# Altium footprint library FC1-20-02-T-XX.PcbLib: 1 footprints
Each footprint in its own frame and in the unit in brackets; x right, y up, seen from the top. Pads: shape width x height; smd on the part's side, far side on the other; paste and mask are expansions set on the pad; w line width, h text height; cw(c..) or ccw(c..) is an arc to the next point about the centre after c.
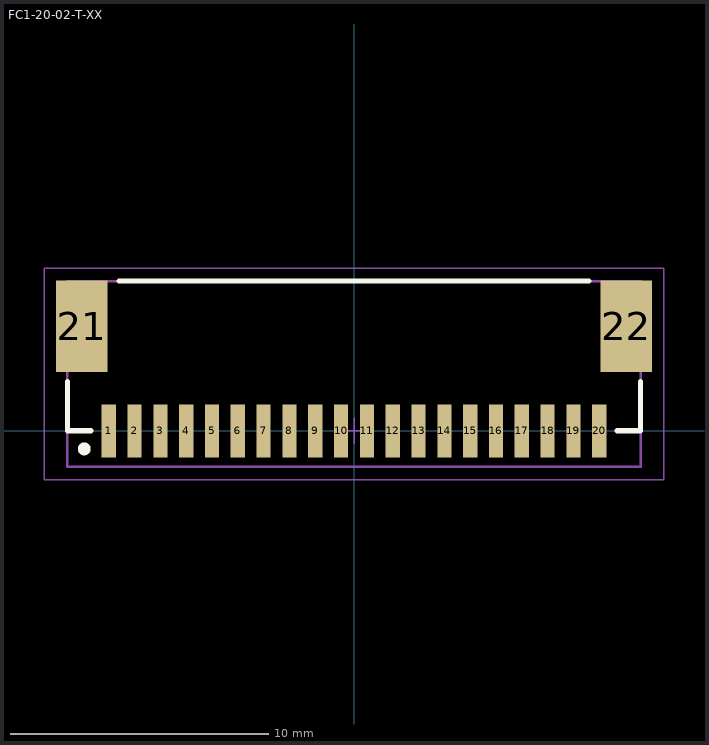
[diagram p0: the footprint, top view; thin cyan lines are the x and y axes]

## FC1-20-02-T-XX [mm] "1.00mm pitch, 20 pin, FFG connector; horizontal"
height 2.77
pads (22):
  rect 0.55x2.05 smd mask+0: 1(-9.5,0) 2(-8.5,0) 3(-7.5,0) 4(-6.5,0) 5(-5.5,0) 6(-4.5,0) 7(-3.5,0) 8(-2.5,0) 9(-1.5,0) 10(-0.5,0) 11(0.5,0) 12(1.5,0) 13(2.5,0) 14(3.5,0) 15(4.5,0) 16(5.5,0) 17(6.5,0) 18(7.5,0) 19(8.5,0) 20(9.5,0)
  rect 2x3.55 smd mask+0: 21(-10.55,4.05) 22(10.55,4.05)
Top Overlay:
  circle w0.25: c-10.45,-0.7 r0.125
  lines w0.2: -11.1,1.9 -11.1,0 -10.2,0 ; -9.1,5.8 9.1,5.8 ; 10.2,0 11.1,0 11.1,1.9
Mechanical 12:
  lines w0.001: -11.1,-1.4 11.1,-1.4 11.1,5.8 -11.1,5.8 -11.1,-1.4
Mechanical 13:
  lines w0.1: -11.1,-1.4 11.1,-1.4 11.1,5.8 -11.1,5.8 -11.1,-1.4
  text ".Designator" at 0.254,0.254 h1.52
Mechanical 15:
  lines w0.05: -0.5,0 0.5,0 ; 0,-0.5 0,0.5 ; -12,-1.9 12,-1.9 12,6.3 -12,6.3 -12,-1.9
